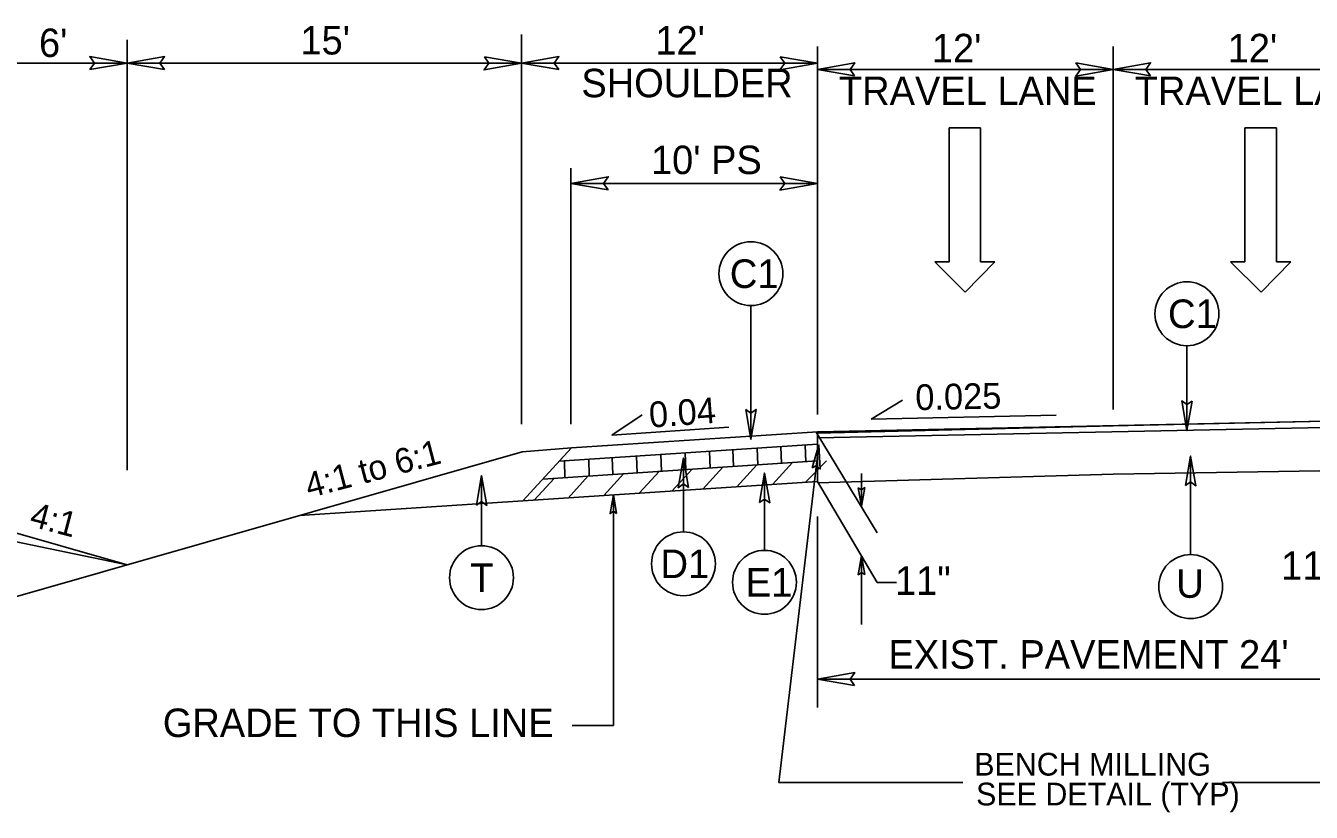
# Model space of a CAD drawing. Extents: x 2176024 to 2177225, y 75947 to 76635.
# Drawn here: x 2176189.7 to 2176241.9, y 76504.3 to 76536.2 of the extents above; entities that cross this region are included whole.
import ezdxf

# ---------------------------------------------------------------- set-up
doc = ezdxf.new("R2010")
doc.units = 0
for name, color, linetype in [('Exist XS Ground Line', 7, 'Continuous'), ('Old_Level_1', 7, 'Continuous'), ('Old_Level_11', 7, 'Continuous'), ('Old_Level_4', 7, 'Continuous'), ('Prop Dimension', 7, 'Continuous'), ('Typical Curb CELL', 7, 'Continuous'), ('Typical Pavement Slope CELL', 7, 'Continuous'), ('Typical Pavement Slope Information CELL', 7, 'Continuous'), ('Typical Shoulder Slope CELL', 7, 'Continuous'), ('Typical Slope Point Local CELL', 7, 'Continuous'), ('Typical Terminator CELL', 7, 'Continuous'), ('Typical Text General CELL', 7, 'Continuous')]:
    doc.layers.add(name, color=color, linetype=linetype)

msp = doc.modelspace()

# ---------------------------------------------------------------- linework, layer by layer
at = {"layer": 'Exist XS Ground Line'}
for q in [(2176245.841, 76518.188), (2176221.841, 76517.635)]:
    msp.add_line((2176233.841, 76517.987), q, dxfattribs=at)
at = {"layer": 'Old_Level_1'}
for p, q in [((2176220.384, 76518.422), (2176220.359, 76519.101)), ((2176221.371, 76518.49), (2176221.346, 76519.166)), ((2176212.589, 76517.916), (2176212.565, 76518.59)), ((2176213.545, 76517.973), (2176213.52, 76518.653)), ((2176214.532, 76518.041), (2176214.507, 76518.717)), ((2176215.519, 76518.102), (2176215.494, 76518.782)), ((2176216.504, 76518.174), (2176216.48, 76518.847)), ((2176217.492, 76518.232), (2176217.467, 76518.912)), ((2176218.442, 76518.292), (2176218.417, 76518.974)), ((2176219.429, 76518.365), (2176219.404, 76519.039)), ((2176211.602, 76517.844), (2176211.578, 76518.525)), ((2176213.175, 76517.117), (2176213.994, 76518.013)), ((2176214.617, 76517.213), (2176215.427, 76518.099)), ((2176215.939, 76517.295), (2176216.767, 76518.184)), ((2176217.196, 76517.383), (2176218.003, 76518.265)), ((2176218.57, 76517.468), (2176219.388, 76518.362)), ((2176220.014, 76517.566), (2176220.833, 76518.462)), ((2176221.34, 76517.655), (2176222.214, 76518.53)), ((2176210.357, 76516.934), (2176211.164, 76517.816)), ((2176211.73, 76517.019), (2176212.548, 76517.913))]:
    msp.add_line(p, q, dxfattribs=at)
at = {"layer": 'Old_Level_11'}
for p, q in [((2176219.144, 76524.82), (2176219.144, 76519.405)), ((2176236.832, 76523.193), (2176236.832, 76519.753)), ((2176216.409, 76515.648), (2176216.409, 76518.644)), ((2176236.983, 76514.724), (2176236.983, 76518.723)), ((2176219.695, 76514.898), (2176219.695, 76518.031)), ((2176208.216, 76515.086), (2176208.216, 76517.928))]:
    msp.add_line(p, q, dxfattribs=at)
for points in [[(2176237.039, 76520.953), (2176236.832, 76519.753), (2176236.619, 76520.959), (2176236.832, 76520.806)], [(2176218.937, 76520.605), (2176219.144, 76519.405), (2176219.357, 76520.612), (2176219.144, 76520.458)], [(2176221.626, 76518.239), (2176221.906, 76519.172), (2176221.959, 76518.193), (2176221.805, 76518.336)], [(2176216.616, 76517.444), (2176216.409, 76518.644), (2176216.196, 76517.437), (2176216.409, 76517.591)], [(2176236.776, 76517.523), (2176236.983, 76518.723), (2176237.196, 76517.517), (2176236.983, 76517.67)], [(2176219.488, 76516.831), (2176219.695, 76518.031), (2176219.908, 76516.825), (2176219.695, 76516.978)], [(2176208.01, 76516.728), (2176208.216, 76517.928), (2176208.43, 76516.721), (2176208.216, 76516.874)]]:
    msp.add_lwpolyline(points, close=True, dxfattribs=at)
for centre in [(2176219.144, 76526.116), (2176236.832, 76524.489), (2176216.409, 76514.352), (2176208.216, 76513.79), (2176219.695, 76513.602), (2176236.983, 76513.428)]:
    msp.add_circle(centre, 1.296, dxfattribs=at)
at = {"layer": 'Old_Level_4'}
for p, q in [((2176227.181, 76526.592), (2176227.181, 76532.024)), ((2176227.181, 76532.024), (2176228.462, 76532.024)), ((2176228.462, 76532.024), (2176228.462, 76526.592)), ((2176239.181, 76526.592), (2176239.181, 76532.024)), ((2176239.181, 76532.024), (2176240.462, 76532.024)), ((2176240.462, 76532.024), (2176240.462, 76526.592)), ((2176227.841, 76525.37), (2176226.599, 76526.592)), ((2176226.599, 76526.592), (2176227.181, 76526.592)), ((2176229.044, 76526.592), (2176227.841, 76525.37)), ((2176228.462, 76526.592), (2176229.044, 76526.592)), ((2176239.841, 76525.37), (2176238.599, 76526.592)), ((2176238.599, 76526.592), (2176239.181, 76526.592)), ((2176241.044, 76526.592), (2176239.841, 76525.37)), ((2176240.462, 76526.592), (2176241.044, 76526.592))]:
    msp.add_line(p, q, dxfattribs=at)
at = {"layer": 'Prop Dimension'}
for p, q in [((2176209.841, 76520.013), (2176209.841, 76535.812)), ((2176193.841, 76518.15), (2176193.841, 76535.602)), ((2176221.841, 76520.401), (2176221.841, 76535.326)), ((2176233.841, 76520.602), (2176233.841, 76535.326)), ((2176193.841, 76534.648), (2176187.841, 76534.648)), ((2176209.841, 76534.648), (2176193.841, 76534.648)), ((2176221.841, 76534.648), (2176209.841, 76534.648)), ((2176233.841, 76534.398), (2176221.947, 76534.398)), ((2176245.841, 76534.398), (2176233.947, 76534.398)), ((2176211.841, 76520.013), (2176211.841, 76530.393)), ((2176221.841, 76529.776), (2176211.841, 76529.776)), ((2176221.796, 76519.689), (2176224.266, 76515.607)), ((2176220.278, 76505.489), (2176221.906, 76519.172)), ((2176223.629, 76516.683), (2176223.629, 76518.011)), ((2176221.841, 76517.688), (2176224.266, 76513.594)), ((2176213.568, 76517.145), (2176213.568, 76507.79)), ((2176221.841, 76516.271), (2176221.841, 76508.52)), ((2176223.629, 76511.893), (2176223.629, 76514.669)), ((2176225.046, 76513.594), (2176224.266, 76513.594)), ((2176221.841, 76509.675), (2176245.841, 76509.675)), ((2176211.895, 76507.79), (2176213.568, 76507.79)), ((2176227.742, 76505.489), (2176220.278, 76505.489)), ((2176238.271, 76505.489), (2176246.864, 76505.489))]:
    msp.add_line(p, q, dxfattribs=at)
at = {"layer": 'Typical Curb CELL'}
msp.add_line((2176221.841, 76517.688), (2176221.841, 76519.703), dxfattribs=at)
at = {"layer": 'Typical Pavement Slope CELL'}
for p, q in [((2176245.841, 76520.203), (2176221.841, 76519.703)), ((2176211.86, 76519.048), (2176221.841, 76519.703)), ((2176245.17, 76519.939), (2176221.841, 76519.453)), ((2176221.841, 76519.199), (2176211.367, 76518.511)), ((2176211.86, 76519.048), (2176209.889, 76516.904)), ((2176221.841, 76518.521), (2176210.703, 76517.79)), ((2176193.841, 76514.314), (2176177.841, 76517.609)), ((2176221.841, 76517.688), (2176200.831, 76516.31))]:
    msp.add_line(p, q, dxfattribs=at)
at = {"layer": 'Typical Pavement Slope Information CELL'}
for p, q in [((2176224.027, 76520.222), (2176225.288, 76520.985)), ((2176213.508, 76519.567), (2176214.731, 76520.39)), ((2176224.027, 76520.222), (2176231.533, 76520.373)), ((2176213.508, 76519.567), (2176218.254, 76519.894))]:
    msp.add_line(p, q, dxfattribs=at)
at = {"layer": 'Typical Shoulder Slope CELL'}
for p, q in [((2176233.841, 76519.953), (2176221.841, 76519.65)), ((2176177.887, 76509.758), (2176209.86, 76518.888)), ((2176211.86, 76519.048), (2176209.86, 76518.888)), ((2176193.841, 76514.314), (2176187.894, 76516.012))]:
    msp.add_line(p, q, dxfattribs=at)
at = {"layer": 'Typical Slope Point Local CELL'}
for p, q in [((2176245.12, 76520.188), (2176233.841, 76519.953)), ((2176221.841, 76519.703), (2176211.86, 76519.048)), ((2176233.841, 76519.953), (2176221.841, 76519.703)), ((2176221.841, 76519.453), (2176245.17, 76519.939)), ((2176221.841, 76519.199), (2176221.841, 76519.703)), ((2176221.841, 76519.703), (2176221.841, 76519.453)), ((2176211.367, 76518.511), (2176221.841, 76519.199)), ((2176211.86, 76519.048), (2176211.367, 76518.511))]:
    msp.add_line(p, q, dxfattribs=at)
at = {"layer": 'Typical Terminator CELL'}
for points in [[(2176192.331, 76534.388), (2176193.841, 76534.648), (2176192.323, 76534.917), (2176192.516, 76534.648)], [(2176195.35, 76534.388), (2176193.841, 76534.648), (2176195.359, 76534.917), (2176195.166, 76534.648)], [(2176208.331, 76534.908), (2176209.841, 76534.648), (2176208.323, 76534.38), (2176208.516, 76534.648)], [(2176211.35, 76534.388), (2176209.841, 76534.648), (2176211.359, 76534.917), (2176211.166, 76534.648)], [(2176220.331, 76534.908), (2176221.841, 76534.648), (2176220.323, 76534.38), (2176220.516, 76534.648)], [(2176223.35, 76534.138), (2176221.841, 76534.398), (2176223.359, 76534.667), (2176223.166, 76534.398)], [(2176223.35, 76534.138), (2176221.841, 76534.398), (2176223.359, 76534.667), (2176223.166, 76534.398)], [(2176232.331, 76534.658), (2176233.841, 76534.398), (2176232.323, 76534.13), (2176232.516, 76534.398)], [(2176235.35, 76534.138), (2176233.841, 76534.398), (2176235.359, 76534.667), (2176235.166, 76534.398)], [(2176213.35, 76529.516), (2176211.841, 76529.776), (2176213.359, 76530.045), (2176213.166, 76529.776)], [(2176220.331, 76530.036), (2176221.841, 76529.776), (2176220.323, 76529.508), (2176220.516, 76529.776)], [(2176213.698, 76516.391), (2176213.568, 76517.145), (2176213.434, 76516.386), (2176213.568, 76516.483)], [(2176223.497, 76517.437), (2176223.629, 76516.683), (2176223.761, 76517.442), (2176223.627, 76517.345)], [(2176223.761, 76513.915), (2176223.629, 76514.669), (2176223.497, 76513.91), (2176223.631, 76514.006)], [(2176223.35, 76509.415), (2176221.841, 76509.675), (2176223.359, 76509.943), (2176223.166, 76509.675)]]:
    msp.add_lwpolyline(points, close=True, dxfattribs=at)

# ---------------------------------------------------------------- texts
at = {"layer": 'Old_Level_11'}
for s, rotation, p in [('C1', 359.9997, (2176218.288, 76525.536)), ('C1', 0.0003, (2176236.063, 76523.909)), ('D1', 359.9997, (2176215.475, 76513.772)), ('T', 359.9997, (2176207.759, 76513.21)), ('E1', 359.9997, (2176218.931, 76513.022)), ('U', 0.0003, (2176236.397, 76512.974))]:
    msp.add_text(s, height=1.16, rotation=rotation, dxfattribs=at).set_placement(p)
for p in [(2176240.655, 76513.703), (2176224.988, 76513.093)]:
    msp.add_text('11"', height=1.1533, dxfattribs=at).set_placement(p)
at = {"layer": 'Typical Pavement Slope Information CELL'}
for s, rotation, p in [('0.025', 1.1457, (2176225.824, 76520.58)), ('0.04', 4.2658, (2176215.049, 76519.869))]:
    msp.add_text(s, height=1.0429, rotation=rotation, dxfattribs=at).set_placement(p)
at = {"layer": 'Typical Slope Point Local CELL'}
for s, rotation, p in [('4:1 to 6:1', 14.7336, (2176201.217, 76517.013)), ('4:1', 345.2664, (2176189.837, 76515.892))]:
    msp.add_text(s, height=1.0064, rotation=rotation, dxfattribs=at).set_placement(p)
at = {"layer": 'Typical Text General CELL'}
for s, height, p in [("6'", 1.1533, (2176190.265, 76534.901)), ("15'", 1.1533, (2176200.871, 76535.003)), ("12' ", 1.1533, (2176215.268, 76534.999)), ("12' ", 1.1533, (2176226.485, 76534.687)), ("12' ", 1.1533, (2176238.485, 76534.687)), ('SHOULDER', 1.1533, (2176212.267, 76533.269)), ('TRAVEL LANE', 1.15334, (2176222.715, 76532.957)), ('TRAVEL LANE', 1.15334, (2176234.715, 76532.957)), ("10' PS", 1.1533, (2176215.09, 76530.153)), ("EXIST. PAVEMENT 24'", 1.15334, (2176224.722, 76510.103)), ('GRADE TO THIS LINE', 1.15334, (2176195.287, 76507.33)), ('BENCH MILLING', 0.92267, (2176228.203, 76505.765)), ('SEE DETAIL (TYP)', 0.92267, (2176228.278, 76504.555))]:
    msp.add_text(s, height=height, dxfattribs=at).set_placement(p)

doc.saveas('drawing.dxf')
